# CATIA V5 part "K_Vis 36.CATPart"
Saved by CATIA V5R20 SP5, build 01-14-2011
Part number: vis 36
Bounding box of the stored display mesh (mm): x -18 to 3, y -7 to 7, z -7 to 7
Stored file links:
  G:\Khaled_CFAO_2011\ST2M\ST2M_GR2\amorin\Khaled\CAD_Modification\K_Vis 36.CATPart
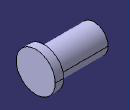
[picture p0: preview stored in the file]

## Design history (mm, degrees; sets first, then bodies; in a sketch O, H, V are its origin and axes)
Body1 (main body)
  Sketch1 on yz-plane, origin (0, 0, 0), H (0, 1, 0), V (0, 0, 1)
    circle A1 centre (0, 0) radius 7
    point P1 (7, 0)
    coincidence: A1 P1, P1 H
  Pad1: profile Sketch1, direction (1, 0, 0), length 3
  Sketch2 on yz-plane, origin (0, 0, 0), H (0, 1, 0), V (0, 0, 1)
    circle A1 centre (0, 0) radius 5
    point P1 (5, 0)
    coincidence: A1 P1, P1 H
  Pad2: profile Sketch2, direction (-1, 0, 0), length 18
  Thread1: diameter 5.5, depth 6, pitch 1, on face of Pad2 from Sketch2.A1, from end face of Pad2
